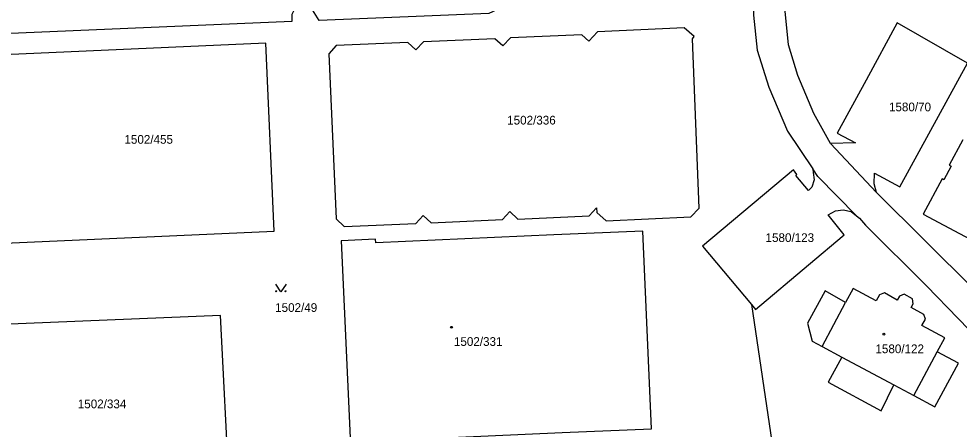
# Model space of a CAD drawing. Extents: x -737240 to -735272, y -1119606 to -1117878.
# Drawn here: x -736364.4 to -736180.7, y -1118320.2 to -1118240.1 of the extents above; entities that cross this region are included whole.
import ezdxf

# ---------------------------------------------------------------- set-up
doc = ezdxf.new("R2010")
doc.units = 0
for name, color, linetype in [('Level 1', 7, 'Continuous'), ('Level 18', 7, 'Continuous'), ('Level 19', 7, 'Continuous'), ('Level 25', 7, 'Continuous'), ('Level 4', 7, 'Continuous')]:
    doc.layers.add(name, color=color, linetype=linetype)

msp = doc.modelspace()

# ---------------------------------------------------------------- linework, layer by layer
at = {"layer": 'Level 1'}
for p, q in [((-736196.9, -1118273.97), (-736205.86, -1118264.4)), ((-736221.31, -1118295.84), (-736216.6, -1118327.37)), ((-736207.53, -1118304.03), (-736203.67, -1118306.1)), ((-736193.48, -1118311.54), (-736189.63, -1118313.6))]:
    msp.add_line(p, q, dxfattribs=at)
for points in [[(-736205.86, -1118264.4), (-736209.12, -1118258.56), (-736212.28, -1118251.18), (-736214.09, -1118245.17), (-736214.79, -1118237.94), (-736214.93, -1118229.61), (-736214.7, -1118183.53), (-736213.85, -1118179.61), (-736210.6, -1118175.18), (-736208.19, -1118173.53)], [(-736221.07, -1118223.43), (-736256.58, -1118221.79), (-736261.77, -1118221.52), (-736262.08, -1118221.69), (-736262.13, -1118222.12), (-736260.56, -1118226.12), (-736270.19, -1118237.96), (-736272.61, -1118239.03), (-736305.72, -1118240.43), (-736308.35, -1118236.17), (-736308.58, -1118236.02), (-736308.84, -1118236.06), (-736309.85, -1118236.8), (-736311.06, -1118239.25), (-736311.07, -1118240.65), (-736375.18, -1118243.32)], [(-736221.07, -1118223.43), (-736220.89, -1118239.4), (-736220.19, -1118246.22), (-736217.93, -1118253.42), (-736214.28, -1118262.01), (-736209.32, -1118269.37)], [(-736196.9, -1118273.97), (-736197.36, -1118272.28), (-736197.27, -1118270.22), (-736192.36, -1118272.89), (-736179.12, -1118248.78), (-736192.84, -1118240.86), (-736198.94, -1118252.09), (-736204.54, -1118262.41), (-736200.99, -1118264.26), (-736205.86, -1118264.4)], [(-736288.45, -1118244.74), (-736302.41, -1118245.32), (-736303.83, -1118246.9), (-736302.43, -1118279.1), (-736300.87, -1118280.61), (-736286.86, -1118280.01), (-736285.42, -1118278.44), (-736283.88, -1118279.92), (-736269.94, -1118279.28), (-736268.5, -1118277.72), (-736266.92, -1118279.18), (-736252.98, -1118278.56), (-736251.56, -1118277), (-736251.49, -1118277.88), (-736249.69, -1118279.52), (-736233.16, -1118278.76), (-736231.55, -1118277.05), (-736232.83, -1118243.99), (-736232.51, -1118243.57), (-736234.44, -1118241.85), (-736251.38, -1118242.62), (-736253.1, -1118244.46), (-736254.47, -1118243.22), (-736268.38, -1118243.81), (-736269.84, -1118245.38), (-736271.41, -1118244), (-736285.37, -1118244.58), (-736286.84, -1118246.15), (-736288.45, -1118244.74)], [(-736370.31, -1118247.27), (-736368.67, -1118283.94), (-736314.51, -1118281.52), (-736316.13, -1118244.82), (-736370.31, -1118247.27)], [(-736180.01, -1118263.7), (-736182.67, -1118268.67), (-736182.31, -1118268.86), (-736183.73, -1118271.53), (-736184.09, -1118271.34), (-736187.77, -1118278.22), (-736176.66, -1118284.14), (-736173.14, -1118277.56)], [(-736209.32, -1118269.37), (-736209.23, -1118270.05), (-736209.04, -1118271.52), (-736209.52, -1118272.91), (-736210.17, -1118273.58), (-736212.64, -1118270.67), (-736212.43, -1118270.47), (-736213.13, -1118269.57), (-736230.85, -1118284.43), (-736221.31, -1118295.84)], [(-736200.79, -1118278.54), (-736208.33, -1118270.84), (-736209.32, -1118269.37)], [(-736068.55, -1118371.85), (-736072.64, -1118370.2), (-736076.44, -1118368.41), (-736088.36, -1118362.67), (-736110.12, -1118350.32), (-736124.12, -1118342.88), (-736126.16, -1118341.48), (-736136.25, -1118333.56), (-736143.63, -1118327.06), (-736151.23, -1118320.2), (-736160.8, -1118310.46), (-736177.91, -1118292.84), (-736196.9, -1118273.97)], [(-736221.31, -1118295.84), (-736220.52, -1118296.79), (-736210.2, -1118288.12), (-736203.19, -1118282.24), (-736206.36, -1118278.37), (-736204.91, -1118277.59), (-736203.38, -1118277.39), (-736201.86, -1118277.7), (-736200.79, -1118278.54)], [(-736200.79, -1118278.54), (-736200.24, -1118278.97), (-736199.05, -1118280.35), (-736187.15, -1118292.22), (-736174.77, -1118304.95), (-736172.1, -1118307.65)], [(-736294.67, -1118283.81), (-736294.71, -1118283.08), (-736301.44, -1118283.43), (-736299.65, -1118323.31), (-736292.98, -1118323.01), (-736293, -1118322.34), (-736258.25, -1118320.8), (-736240.85, -1118320.09), (-736242.53, -1118281.51), (-736259.92, -1118282.25), (-736294.67, -1118283.81)], [(-736185.01, -1118305.05), (-736183.56, -1118302.36), (-736188.04, -1118299.95), (-736187.33, -1118298.7), (-736187.62, -1118297.77), (-736190.11, -1118296.41), (-736189.71, -1118295.69), (-736189.87, -1118294.76), (-736191.46, -1118293.85), (-736192.4, -1118294.21), (-736192.83, -1118294.97), (-736195.3, -1118293.56), (-736196.31, -1118293.93), (-736196.98, -1118295.15), (-736201.47, -1118292.73), (-736202.92, -1118295.43)], [(-736202.92, -1118295.43), (-736206.92, -1118293.14), (-736210.39, -1118299.46), (-736209.47, -1118302.98), (-736207.53, -1118304.03)], [(-736323.26, -1118332.43), (-736325.03, -1118297.95), (-736380.42, -1118300.27), (-736381.78, -1118300.94), (-736382.38, -1118302.33), (-736380.97, -1118335.25)], [(-736189.63, -1118313.6), (-736185.5, -1118315.82), (-736180.9, -1118307.27), (-736185.01, -1118305.05)], [(-736203.67, -1118306.1), (-736206.33, -1118310.98), (-736195.98, -1118316.55), (-736193.48, -1118311.54)]]:
    msp.add_lwpolyline(points, dxfattribs=at)
at = {"layer": 'Level 25'}
msp.add_lwpolyline([(-736312.21, -1118291.85), (-736313.21, -1118293.35), (-736314.21, -1118291.85)], dxfattribs=at)
for centre in [(-736314.11, -1118293.25), (-736312.31, -1118293.25)]:
    msp.add_circle(centre, 0.1, dxfattribs=at)
for centre in [(-736279.9, -1118300.28), (-736195.44, -1118301.63)]:
    msp.add_ellipse(centre, major_axis=(0.18, 0), ratio=0.9848078, dxfattribs=at)
at = {"layer": 'Level 4'}
for p, q in [((-736207.53, -1118304.03), (-736202.92, -1118295.43)), ((-736189.63, -1118313.6), (-736185.01, -1118305.05)), ((-736203.67, -1118306.1), (-736193.48, -1118311.54))]:
    msp.add_line(p, q, dxfattribs=at)

# ---------------------------------------------------------------- texts
at = {"layer": 'Level 18'}
for s, p in [('1580/70', (-736194.455, -1118258.14)), ('1502/336', (-736269.02, -1118260.72)), ('1502/455', (-736343.77, -1118264.47)), ('1580/123', (-736218.56, -1118283.64)), ('1502/49', (-736314.335, -1118297.28)), ('1502/334', (-736352.88, -1118316.08))]:
    msp.add_text(s, height=1.7, dxfattribs=at).set_placement(p)
at = {"layer": 'Level 19'}
for s, p in [('1502/331', (-736279.42, -1118303.91)), ('1580/122', (-736197.095, -1118305.33))]:
    msp.add_text(s, height=1.7, dxfattribs=at).set_placement(p)

doc.saveas('drawing.dxf')
